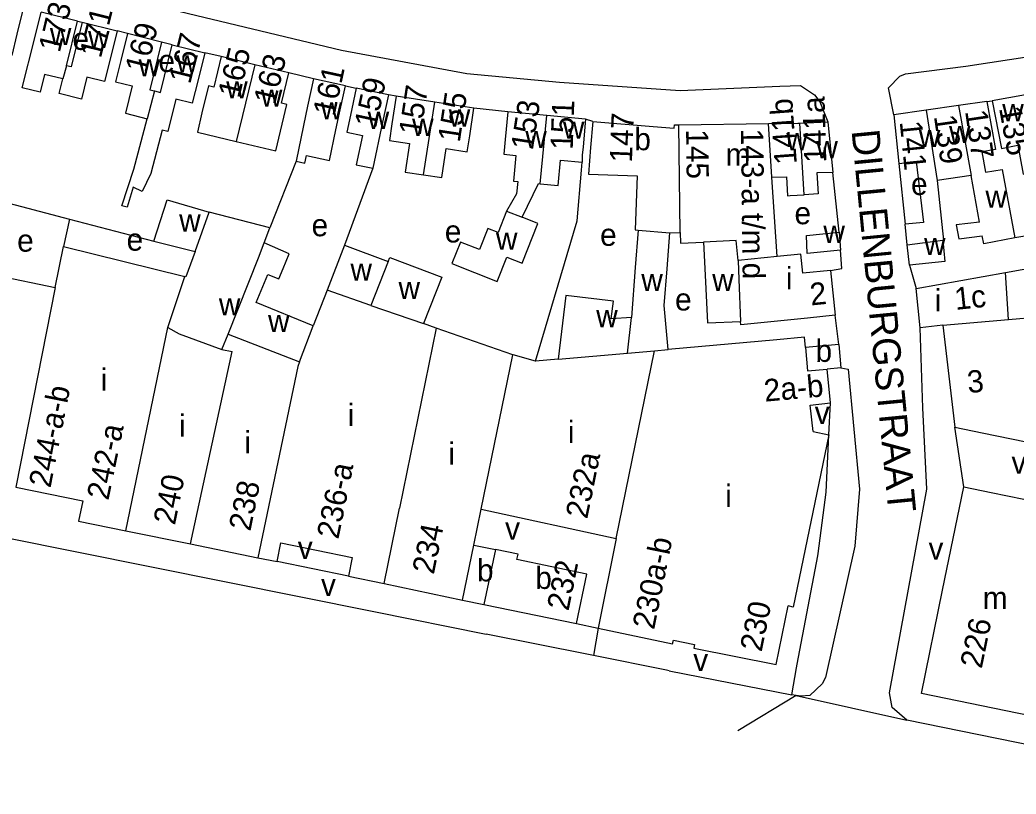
# Model space of a CAD drawing. Extents: x 157569 to 159501, y 382907 to 384670.
# Drawn here: x 158557 to 158735.9, y 383006.6 to 383145.7 of the extents above; entities that cross this region are included whole.
import ezdxf

# ---------------------------------------------------------------- set-up
doc = ezdxf.new("R2010")
doc.units = 0
for name, color, linetype in [('BLT_Basislijn', 7, 'Continuous'), ('BLT_Bebouwing', 7, 'Continuous'), ('BLT_Centroide', 7, 'Continuous'), ('BLT_Huisnummer', 7, 'Continuous'), ('BLT_Huisnummer_ tussenligend', 7, 'Continuous'), ('BLT_Huisnummer_reeks', 7, 'Continuous'), ('BLT_Onderdoorgang_en_onderverdeling', 7, 'Continuous'), ('BLT_Onderverdeling_panden', 7, 'Continuous'), ('BLT_Straatnaam', 7, 'Continuous'), ('BLT_Vlakafsluiter', 7, 'Continuous')]:
    doc.layers.add(name, color=color, linetype=linetype)

msp = doc.modelspace()

# ---------------------------------------------------------------- linework, layer by layer
at = {"layer": 'BLT_Basislijn'}
for p, q in [((158567.29, 383145.49), (158568.15, 383145.28)), ((158576.27, 383143.26), (158574.4, 383143.73)), ((158584.32, 383141.26), (158582.41, 383141.73)), ((158593.09, 383139.12), (158590.18, 383139.8)), ((158609.66, 383135.11), (158605.23, 383136.23)), ((158615.42, 383133.88), (158617.37, 383133.46)), ((158624.51, 383131.99), (158623.13, 383132.23)), ((158730.59, 383131.05), (158731.58, 383131.18)), ((158644.57, 383129.18), (158638.5, 383129.84)), ((158659.83, 383127.46), (158658.55, 383127.86)), ((158606.57, 383120.32), (158601.86, 383108.36)), ((158620.31, 383119.05), (158615.26, 383105.26)), ((158704.07, 383107.55), (158702.96, 383118.28)), ((158714.8, 383119.94), (158715.93, 383109)), ((158551.99, 383113.55), (158565.89, 383109.92)), ((158565.89, 383109.92), (158564.79, 383105.02)), ((158565.89, 383109.92), (158580.99, 383105.97)), ((158716.7, 383101.66), (158717.92, 383097.44)), ((158704.01, 383087.37), (158703.35, 383092.65)), ((158702.2, 383071.18), (158702.51, 383076.91)), ((158726.47, 383061.82), (158724.84, 383072.54)), ((158615.96, 383045.76), (158603.15, 383048.39)), ((158656.94, 383037.28), (158660.78, 383036.44)), ((158660.78, 383036.44), (158659.94, 383031.51)), ((158673.57, 383028.76), (158695.6, 383024.47)), ((158695.6, 383024.47), (158696.45, 383029.31))]:
    msp.add_line(p, q, dxfattribs=at)
for points in [[(158713.92, 383128.64), (158712.94, 383133.49), (158714.96, 383135.61), (158716, 383136.04), (158726.81, 383137.39), (158746.81, 383140.46), (158763.56, 383144.53), (158777.06, 383148.27), (158789.46, 383152.3), (158807.27, 383158.8), (158820.57, 383164.35), (158834.91, 383169.88), (158851.49, 383178.15), (158858.84, 383181.12), (158960.36, 383232.84), (158963.81, 383232.99), (158965.38, 383232.2), (158967.85, 383228.7)], [(158136.23, 383207.98), (158138.34, 383210.7), (158142.33, 383213.13), (158148.56, 383213.38), (158153.24, 383212.69), (158183.67, 383207.66), (158286.08, 383185.1), (158316.24, 383179.46), (158331.59, 383176.95), (158343.62, 383175.44), (158386.57, 383170.97), (158477.11, 383166.26), (158514.99, 383162.58), (158552.21, 383155.31), (158614.72, 383140.3), (158637.24, 383136.07), (158653.85, 383134.55), (158675.54, 383133.02), (158693.44, 383133.82), (158697.11, 383133.9), (158699.66, 383132.24), (158700.59, 383130.97), (158702.07, 383127.4)], [(158649.56, 383084.37), (158657.05, 383109.63), (158657.83, 383118.73), (158657.92, 383120.18)], [(158767.42, 383106.37), (158764.69, 383121.14), (158753.62, 383118.79), (158755.51, 383109.87), (158735.64, 383106.53)], [(158702.53, 383100.7), (158704.57, 383101.06), (158704.35, 383104.34)], [(158716.21, 383019.87), (158713.59, 383022.19), (158713.11, 383024.82), (158719.82, 383061.4), (158719.13, 383076.02), (158718.61, 383090.37)], [(158704.39, 383083.22), (158705.67, 383082.99), (158707.76, 383061.4), (158706.88, 383051.17), (158701.6, 383027.57), (158701.04, 383026.41), (158698.8, 383024.34), (158697.19, 383024.21), (158696.38, 383024.34)], [(158700.23, 383049.4), (158700.31, 383049.85), (158701.72, 383060.89), (158702.2, 383071.18)], [(158554.05, 383052.75), (158620.52, 383039.41), (158640.72, 383035.37)], [(158696.45, 383029.31), (158696.56, 383029.95), (158700.23, 383049.4)], [(158659.94, 383031.51), (158659.04, 383031.69), (158640.72, 383035.37)], [(158673.57, 383028.76), (158673.1, 383028.85), (158659.94, 383031.51)], [(158696.38, 383024.34), (158695.6, 383024.47)], [(158781.47, 383006.61), (158716.21, 383019.87)]]:
    msp.add_lwpolyline(points, dxfattribs=at)
at = {"layer": 'BLT_Bebouwing'}
for p, q in [((158567.29, 383145.49), (158560.77, 383147.11)), ((158565.3, 383137.48), (158567.29, 383145.49)), ((158568.15, 383145.28), (158574.4, 383143.73)), ((158582.41, 383141.73), (158576.27, 383143.26)), ((158584.32, 383141.26), (158590.18, 383139.8)), ((158599.16, 383137.67), (158593.09, 383139.12)), ((158605.23, 383136.23), (158599.16, 383137.67)), ((158615.42, 383133.88), (158609.66, 383135.11)), ((158623.13, 383132.23), (158617.37, 383133.46)), ((158631.45, 383130.92), (158624.51, 383131.99)), ((158638.5, 383129.84), (158631.45, 383130.92)), ((158730.59, 383131.05), (158725.51, 383130.31)), ((158737.53, 383132.28), (158731.58, 383131.18)), ((158651.56, 383128.52), (158644.57, 383129.18)), ((158719.68, 383129.47), (158713.92, 383128.64)), ((158725.51, 383130.31), (158719.68, 383129.47)), ((158658.55, 383127.86), (158651.56, 383128.52)), ((158659.83, 383127.46), (158670.71, 383126.59)), ((158697.01, 383127.17), (158702.07, 383127.4)), ((158702.07, 383127.4), (158702.96, 383118.28)), ((158713.92, 383128.64), (158714.8, 383119.94)), ((158675.32, 383126.88), (158691.39, 383127.09)), ((158692.96, 383103.2), (158691.97, 383117.44)), ((158727.77, 383117.74), (158721.67, 383116.86)), ((158729.28, 383109.38), (158727.77, 383117.74)), ((158601.86, 383108.36), (158590.96, 383111.18)), ((158644.37, 383111.37), (158642.83, 383107.51)), ((158649.97, 383109.14), (158647.17, 383110.26)), ((158640.98, 383108.24), (158639.47, 383104.44)), ((158642.83, 383107.51), (158640.98, 383108.24)), ((158647.14, 383102.02), (158649.97, 383109.14)), ((158704.07, 383107.55), (158704.35, 383104.34)), ((158716.32, 383105.33), (158715.93, 383109)), ((158580.99, 383105.97), (158588.42, 383104.13)), ((158636.08, 383105.79), (158634.55, 383101.93)), ((158639.47, 383104.44), (158636.08, 383105.79)), ((158563.29, 383097.65), (158564.79, 383105.02)), ((158564.79, 383105.02), (158586.57, 383099.61)), ((158615.26, 383105.26), (158612.11, 383097.16)), ((158615.26, 383105.26), (158623.09, 383102.29)), ((158716.7, 383101.66), (158716.32, 383105.33)), ((158623.09, 383102.29), (158623.37, 383103.01)), ((158623.37, 383103.01), (158632.73, 383099.48)), ((158642.68, 383098.7), (158644.42, 383103.09)), ((158644.42, 383103.09), (158647.14, 383102.02)), ((158733.97, 383100.34), (158747.21, 383102.73)), ((158549.33, 383100.49), (158563.29, 383097.65)), ((158634.55, 383101.93), (158642.68, 383098.7)), ((158702.53, 383100.7), (158697.55, 383100.22)), ((158702.53, 383100.7), (158703.35, 383092.65)), ((158717.92, 383097.44), (158733.97, 383100.34)), ((158632.73, 383099.48), (158629.42, 383091.14)), ((158612.11, 383097.16), (158609.63, 383090.77)), ((158718.61, 383090.37), (158717.92, 383097.44)), ((158631.7, 383090.35), (158629.42, 383091.14)), ((158645.46, 383085.56), (158631.7, 383090.35)), ((158722.69, 383090.85), (158718.61, 383090.37)), ((158722.69, 383090.85), (158724.84, 383072.54)), ((158704.01, 383087.37), (158704.39, 383083.22)), ((158653.64, 383084.78), (158649.56, 383084.37)), ((158704.39, 383083.22), (158701.92, 383082.99)), ((158702.51, 383076.91), (158701.92, 383082.99)), ((158699.39, 383071.79), (158702.2, 383071.18)), ((158722.65, 383043.26), (158726.47, 383061.82)), ((158638.47, 383051.36), (158639.8, 383057.78)), ((158575.96, 383053.92), (158587.61, 383051.55)), ((158664.05, 383052.51), (158660.78, 383036.44)), ((158587.61, 383051.55), (158599.7, 383049.09)), ((158638.47, 383051.36), (158642.34, 383050.57)), ((158599.7, 383049.09), (158603.15, 383048.39)), ((158616.64, 383049.13), (158615.96, 383045.76)), ((158615.96, 383045.76), (158622.35, 383044.46)), ((158622.35, 383044.46), (158636.42, 383041.45)), ((158636.42, 383041.45), (158640.27, 383040.68)), ((158640.27, 383040.68), (158656.94, 383037.28)), ((158692.75, 383029.89), (158694.91, 383040.42)), ((158660.78, 383036.44), (158674.18, 383033.61)), ((158674.18, 383033.61), (158674.32, 383034.28)), ((158674.32, 383034.28), (158678.12, 383033.51))]:
    msp.add_line(p, q, dxfattribs=at)
for points in [[(158557.6, 383147.99), (158556.42, 383143.13), (158555.49, 383139.33), (158552.56, 383140.05), (158551.32, 383134.93), (158548.13, 383135.71), (158548.75, 383138.24)], [(158564.64, 383135.13), (158561.4, 383135.93), (158560.6, 383132.71), (158557.39, 383133.5), (158559.57, 383142.26), (158560.77, 383147.11)], [(158568.15, 383145.28), (158566.16, 383137.27), (158565.3, 383137.48)], [(158574.4, 383143.73), (158573.2, 383138.88), (158572.14, 383134.63), (158568.98, 383135.42), (158568.01, 383131.5), (158563.99, 383132.5), (158564.64, 383135.13)], [(158576.27, 383143.26), (158575.07, 383138.41), (158574.12, 383134.61), (158577.13, 383133.86), (158575.91, 383128.94), (158579.79, 383127.97)], [(158582.41, 383141.73), (158580.28, 383133.17), (158581.1, 383132.96)], [(158590.18, 383139.8), (158588.97, 383134.95), (158587.92, 383130.75), (158584.95, 383131.49), (158583.5, 383125.68), (158582.52, 383125.92), (158580.48, 383118.12), (158578.89, 383114.89), (158577.28, 383115.64), (158576.2, 383112.09), (158575.27, 383112.32), (158577.43, 383118.92), (158579.79, 383127.97)], [(158581.1, 383132.96), (158582.19, 383132.69), (158584.32, 383141.26)], [(158593.09, 383139.12), (158591.79, 383133.64), (158590.81, 383133.87), (158589.65, 383129.01), (158588.83, 383125.55), (158595.77, 383123.89)], [(158595.77, 383123.89), (158602.93, 383122.19), (158604.91, 383130.54), (158603.93, 383130.77), (158605.23, 383136.23)], [(158609.66, 383135.11), (158608.61, 383130.23), (158607.87, 383126.77), (158606.57, 383120.32)], [(158606.57, 383120.32), (158608.14, 383120), (158608.41, 383121.35), (158612.54, 383120.47), (158613.72, 383125.95), (158614.37, 383128.99), (158615.42, 383133.88)], [(158617.37, 383133.46), (158616.32, 383128.57), (158615.67, 383125.53), (158618.5, 383124.93), (158617.37, 383119.68), (158620.31, 383119.05)], [(158623.13, 383132.23), (158622.08, 383127.34), (158620.31, 383119.05)], [(158624.51, 383131.99), (158623.75, 383127.05), (158623.32, 383124.04), (158626.95, 383123.48), (158626.16, 383118.38), (158629.44, 383117.87)], [(158730.59, 383131.05), (158732.18, 383122.45), (158729.68, 383121.99), (158730.35, 383118.37), (158733.36, 383118.81), (158735.64, 383106.53)], [(158731.58, 383131.18), (158733.21, 383122.64), (158736.14, 383123.2), (158737.1, 383118.02), (158740.08, 383118.57)], [(158629.44, 383117.87), (158632.71, 383117.37), (158633.52, 383122.62), (158637.3, 383122.04), (158637.74, 383124.9), (158638.5, 383129.84)], [(158644.57, 383129.18), (158644.1, 383124.2), (158643.88, 383121.57), (158646.01, 383121.36), (158645.58, 383116.74), (158646.35, 383116.66), (158646.14, 383114.44), (158644.37, 383111.37)], [(158658.55, 383127.86), (158658.08, 383122.89), (158657.95, 383121.4), (158657.92, 383120.18)], [(158659.83, 383127.46), (158659.45, 383122.77), (158659.07, 383117.98), (158667.79, 383117.72)], [(158691.39, 383127.09), (158696.68, 383127.16), (158697.01, 383127.17)], [(158670.71, 383126.59), (158674.44, 383126.29), (158674.49, 383126.87), (158675.32, 383126.88)], [(158650.41, 383116.28), (158653.61, 383115.98), (158654.04, 383120.53), (158657.92, 383120.18)], [(158714.8, 383119.94), (158717.93, 383120.26), (158719.25, 383109.34), (158715.93, 383109)], [(158702.96, 383118.28), (158700.07, 383118.22), (158700.29, 383114.44), (158697.79, 383114.29)], [(158667.79, 383117.72), (158667.44, 383107.98), (158667.96, 383107.94)], [(158691.97, 383117.44), (158694.64, 383117.49), (158694.82, 383114.11), (158695.3, 383114.14), (158697.79, 383114.29)], [(158721.67, 383116.86), (158722.85, 383106.14), (158722.71, 383106.15)], [(158647.17, 383110.26), (158650.08, 383116.31), (158650.41, 383116.28)], [(158580.99, 383105.97), (158583.42, 383113.37), (158590.96, 383111.18)], [(158729.28, 383109.38), (158725.07, 383108.9), (158725.55, 383106.38), (158729.77, 383106.92)], [(158600.83, 383105.64), (158601.86, 383108.36)], [(158667.96, 383107.94), (158667.42, 383101.21), (158666.76, 383092.24)], [(158673.67, 383107.46), (158675.54, 383107.49)], [(158675.54, 383107.49), (158675.56, 383105.61), (158679.74, 383105.8)], [(158704.35, 383104.34), (158698.36, 383103.77), (158698.2, 383106.97), (158704.07, 383107.55)], [(158673.38, 383086.48), (158672.66, 383094.39), (158673.17, 383100.99), (158673.67, 383107.46)], [(158679.74, 383105.8), (158679.95, 383101.05), (158680.45, 383091.29), (158686.34, 383091.5)], [(158722.71, 383106.15), (158723.04, 383102.3), (158716.7, 383101.66)], [(158735.64, 383106.53), (158730.06, 383105.48), (158729.77, 383106.92)], [(158588.42, 383104.13), (158586.77, 383099.56), (158586.57, 383099.61)], [(158604.21, 383101.03), (158605.33, 383103.67), (158600.83, 383105.64)], [(158697.55, 383100.22), (158697.22, 383103.64), (158692.96, 383103.2)], [(158609.63, 383090.77), (158599.36, 383094.95), (158601.46, 383099.98), (158603.43, 383099.18), (158604.21, 383101.03)], [(158663.16, 383092), (158663.57, 383095.18), (158655.02, 383096.22), (158653.64, 383084.78)], [(158666.76, 383092.24), (158663.16, 383092)], [(158703.35, 383092.65), (158698.38, 383092.15), (158686.4, 383090.94), (158686.34, 383091.5)], [(158697.85, 383088.71), (158692.87, 383088.26), (158673.38, 383086.48)], [(158698.02, 383086.83), (158697.85, 383088.71)], [(158704.01, 383087.37), (158698.02, 383086.83)], [(158649.56, 383084.37), (158645.56, 383085.53), (158645.46, 383085.56)], [(158699.39, 383071.79), (158698.85, 383076.5), (158702.51, 383076.91)], [(158724.84, 383072.54), (158729.74, 383071.53), (158747.89, 383067.79)], [(158702.2, 383071.18), (158695.84, 383040.21), (158694.91, 383040.42)], [(158556.2, 383061.77), (158568.24, 383059.32), (158567.49, 383055.64), (158575.96, 383053.92)], [(158726.47, 383061.82), (158731.37, 383060.82), (158746.02, 383057.81)], [(158639.8, 383057.78), (158664.05, 383052.51)], [(158603.15, 383048.39), (158603.83, 383051.74), (158616.64, 383049.13)], [(158656.94, 383037.28), (158658.74, 383046.15), (158646.21, 383048.79), (158646.41, 383049.74), (158642.34, 383050.57)], [(158738.39, 383020.67), (158718.84, 383024.69), (158722.65, 383043.26)], [(158678.12, 383033.51), (158678, 383032.84), (158692.75, 383029.89)]]:
    msp.add_lwpolyline(points, dxfattribs=at)
at = {"layer": 'BLT_Onderdoorgang_en_onderverdeling'}
for p, q in [((158636.42, 383041.45), (158638.47, 383051.36)), ((158642.34, 383050.57), (158640.27, 383040.68))]:
    msp.add_line(p, q, dxfattribs=at)
at = {"layer": 'BLT_Onderverdeling_panden'}
for p, q in [((158565.3, 383137.48), (158564.64, 383135.13)), ((158599.16, 383137.67), (158595.77, 383123.89)), ((158581.1, 383132.96), (158579.79, 383127.97)), ((158629.44, 383117.87), (158631.45, 383130.92)), ((158719.68, 383129.47), (158721.67, 383116.86)), ((158725.51, 383130.31), (158727.77, 383117.74)), ((158650.41, 383116.28), (158651.56, 383128.52)), ((158697.79, 383114.29), (158697.01, 383127.17)), ((158675.54, 383107.49), (158675.32, 383126.88)), ((158691.97, 383117.44), (158691.39, 383127.09)), ((158588.42, 383104.13), (158590.96, 383111.18)), ((158644.37, 383111.37), (158647.17, 383110.26)), ((158667.96, 383107.94), (158673.67, 383107.46)), ((158716.32, 383105.33), (158722.71, 383106.15)), ((158599.83, 383102.99), (158600.83, 383105.64)), ((158594.34, 383089.27), (158599.83, 383102.99)), ((158623.09, 383102.29), (158619.96, 383094.43)), ((158685.95, 383102.49), (158686.07, 383099.08)), ((158734.52, 383091.9), (158733.97, 383100.34)), ((158583.53, 383090.45), (158586.57, 383099.61)), ((158686.07, 383099.08), (158686.34, 383091.5)), ((158563.29, 383097.65), (158556.2, 383061.77)), ((158619.96, 383094.43), (158612.11, 383097.16)), ((158619.96, 383094.43), (158629.42, 383091.14)), ((158666.05, 383085.85), (158666.76, 383092.24)), ((158722.69, 383090.85), (158734.52, 383091.9)), ((158734.52, 383091.9), (158747.83, 383093.07)), ((158575.96, 383053.92), (158583.53, 383090.45)), ((158607.15, 383084.29), (158609.63, 383090.77)), ((158631.7, 383090.35), (158625.11, 383058)), ((158593.24, 383086.51), (158594.34, 383089.27)), ((158594.34, 383089.27), (158607.15, 383084.29)), ((158587.61, 383051.55), (158595.06, 383086.12)), ((158593.24, 383086.51), (158595.06, 383086.12)), ((158664.05, 383052.51), (158670.93, 383086.27)), ((158666.05, 383085.85), (158670.93, 383086.27)), ((158670.93, 383086.27), (158673.38, 383086.48)), ((158698.02, 383086.83), (158698.39, 383082.67)), ((158639.8, 383057.78), (158645.46, 383085.56)), ((158653.64, 383084.78), (158666.05, 383085.85)), ((158698.39, 383082.67), (158701.92, 383082.99)), ((158622.35, 383044.46), (158625.11, 383058))]:
    msp.add_line(p, q, dxfattribs=at)
for points in [[(158685.95, 383102.49), (158685.59, 383106.07), (158679.74, 383105.8)], [(158692.96, 383103.2), (158685.95, 383102.49)], [(158583.53, 383090.45), (158585.57, 383089.28), (158593.24, 383086.51)], [(158607.15, 383084.29), (158606.84, 383083.46), (158599.7, 383049.09)]]:
    msp.add_lwpolyline(points, dxfattribs=at)
at = {"layer": 'BLT_Vlakafsluiter'}
for q in [(158685.9, 383018), (158716.21, 383019.87)]:
    msp.add_line((158696.38, 383024.34), q, dxfattribs=at)

# ---------------------------------------------------------------- texts
at = {"layer": 'BLT_Centroide'}
for s, p in [('w', (158562.34, 383141.2)), ('e', (158566.4, 383140.32)), ('w', (158569.19, 383140.66)), ('w', (158578.27, 383135.55)), ('e', (158581.83, 383136.36)), ('w', (158585.05, 383136.28)), ('w', (158594, 383131.61)), ('w', (158600.23, 383130.12)), ('w', (158611, 383127.83)), ('w', (158619.41, 383126.14)), ('w', (158633.97, 383126.55)), ('w', (158733.37, 383127.52)), ('w', (158627.39, 383124.88)), ('w', (158654.48, 383124.38)), ('w', (158647.72, 383122.7)), ('b', (158667.3, 383122.3)), ('w', (158694.59, 383122.31)), ('w', (158718.39, 383122.88)), ('w', (158723.81, 383123.61)), ('w', (158699.98, 383120.86)), ('m', (158683.69, 383119.55)), ('e', (158716.99, 383114.25)), ('w', (158730.36, 383111.95)), ('e', (158696.06, 383109)), ('w', (158585.56, 383107.69)), ('e', (158609.34, 383106.84)), ('e', (158633.26, 383105.72)), ('w', (158642.45, 383104.41)), ('e', (158661.15, 383105.12)), ('w', (158701.25, 383105.66)), ('e', (158556.46, 383104.07)), ('e', (158576.12, 383104.25)), ('w', (158719.33, 383103.47)), ('w', (158616.32, 383098.86)), ('i', (158694.51, 383097.28)), ('w', (158624.95, 383095.57)), ('w', (158668.55, 383096.98)), ('w', (158681.28, 383097)), ('i', (158721.24, 383093.36)), ('w', (158592.69, 383092.62)), ('e', (158674.61, 383093.5)), ('w', (158660.45, 383090.5)), ('w', (158601.52, 383089.62)), ('b', (158699.84, 383084.27)), ('i', (158571.48, 383079.09)), ('i', (158615.83, 383072.73)), ('v', (158699.71, 383073.13)), ('i', (158585.52, 383070.84)), ('i', (158655.36, 383069.67)), ('i', (158597.28, 383067.83)), ('i', (158633.91, 383065.8)), ('v', (158735.02, 383064.19)), ('i', (158683.62, 383058.21)), ('v', (158644.09, 383052.34)), ('v', (158606.86, 383048.88)), ('v', (158720.13, 383048.74)), ('b', (158639.04, 383044.82)), ('b', (158649.52, 383043.47)), ('v', (158611.03, 383042.2)), ('m', (158729.87, 383039.86)), ('v', (158677.88, 383028.72))]:
    msp.add_text(s, height=4, dxfattribs=at).set_placement(p)
at = {"layer": 'BLT_Huisnummer'}
for s, rotation, p in [('173', 76.0648, (158564.1, 383139.69)), ('171', 76.0305, (158571.49, 383138.7)), ('169', 76.0314, (158579.66, 383135.96)), ('167', 76.0305, (158587.53, 383134.05)), ('165', 76.6229, (158596.35, 383131.51)), ('163', 76.6203, (158602.77, 383130.33)), ('161', 77.8876, (158613.44, 383128.26)), ('159', 77.8988, (158620.89, 383126.14)), ('157', 81.2403, (158628.92, 383124.81)), ('155', 81.3202, (158635.94, 383123.6)), ('153', 81.3202, (158649.06, 383122.16)), ('151', 88.0434, (158656.23, 383122.34)), ('141b', 94.1219, (158696.49, 383119.87)), ('141a', 91.6268, (158701.79, 383120.11)), ('137', 278.2266, (158726.69, 383129.31)), ('147', 87.6497, (158666.86, 383120.04)), ('141', 275.7158, (158714.95, 383127.42)), ('2', 5.7859, (158699.02, 383094.4)), ('1c', 5.9678, (158724.99, 383093.6)), ('3', 5.083, (158727.24, 383078.66)), ('232a', 78.5088, (158658.83, 383055.93)), ('240', 78.5114, (158584.79, 383054.82)), ('238', 78.485, (158598.34, 383053.72)), ('234', 78.4851, (158631.28, 383045.96)), ('232', 78.5088, (158655.47, 383039.4)), ('226', 78.3937, (158729.68, 383029.03))]:
    msp.add_text(s, height=4, rotation=rotation, dxfattribs=at).set_placement(p)
at = {"layer": 'BLT_Huisnummer_ tussenligend'}
for s, rotation, p in [('135', 280.5202, (158732.78, 383129.85)), ('139', 278.2266, (158721.09, 383128.41))]:
    msp.add_text(s, height=4, rotation=rotation, dxfattribs=at).set_placement(p)
at = {"layer": 'BLT_Huisnummer_reeks'}
for s, rotation, p in [('145', 270.644, (158676.59, 383126.04)), ('143-a t/m d', 270.644, (158686.45, 383126.16)), ('2a-b', 5.2138, (158690.74, 383077.11)), ('244-a-b', 78.8105, (158562.44, 383061.51)), ('242-a', 78.3039, (158572.84, 383059.27)), ('236-a', 78.4822, (158614.14, 383052.28)), ('230a-b', 78.5346, (158670.84, 383036.03)), ('230', 78.5346, (158690.15, 383032.04))]:
    msp.add_text(s, height=4, rotation=rotation, dxfattribs=at).set_placement(p)
at = {"layer": 'BLT_Straatnaam'}
msp.add_text('DILLENBURGSTRAAT', height=5, rotation=275.5117, dxfattribs=at).set_placement((158706.3, 383125.82))

doc.saveas('drawing.dxf')
